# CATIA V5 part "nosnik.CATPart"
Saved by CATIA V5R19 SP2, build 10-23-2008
Part number: nosnik
Material "Steel": density 7860 kg/m3, Young's modulus 2e+11 Pa, Poisson ratio 0.266, thermal expansion 1.17e-05 1/K
Bounding box of the stored display mesh (mm): x -120 to 120, y -15 to 15, z -22.5 to 22.5
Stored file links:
  C:\Documents and Settings\JiriPesek\Dokumenty\catia\nosnik.CATPart
  D:\Program Files\Dassault Systemes\B19\intel_a\startup\materials\Catalog.CATMaterial
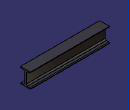
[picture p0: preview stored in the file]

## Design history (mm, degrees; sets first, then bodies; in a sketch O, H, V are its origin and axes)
AxisSystem1: origin (0, 0, 0), X (1, 0, 0), Y (0, 1, 0), Z (0, 0, 1)
Body1 (main body)
  Sketch1 on YZ plane of AxisSystem1, origin (0, 0, 0), H (0, 1, 0), V (0, 0, 1)
    line L1 (2.5, 14.7411) -> (2.5, -14.7411)
    construction line L2 (2.5, -18.4064) -> (-2.5, -18.4064)
    line L3 (-2.5, -14.7411) -> (-2.5, 14.7411)
    construction line L4 (-2.5, 18.4064) -> (2.5, 18.4064)
    point P1 (2.5, 18.4064)
    point P2 (2.5, -18.4064)
    point P3 (-2.5, -18.4064)
    point P4 (-2.5, 18.4064)
    point P5 (0, 20.3479)
    line L5 (15, 22.5) -> (15, 21.3327)
    line L6 (13.1743, 19.3403) -> (6.1514, 18.7258)
    line L7 (-15, 21.3327) -> (-15, 22.5)
    line L8 (-15, 22.5) -> (15, 22.5)
    point P8 (0, -20.3479)
    line L9 (15, -21.3327) -> (15, -22.5)
    line L10 (15, -22.5) -> (-15, -22.5)
    line L11 (-15, -22.5) -> (-15, -21.3327)
    line L12 (-13.1743, -19.3403) -> (-6.1514, -18.7258)
    point P9 (15, -19.5)
    point P11 (-15, -22.5)
    point P12 (-15, -19.5)
    line L13 (6.1514, -18.7258) -> (13.1743, -19.3403)
    line L14 (-6.1514, 18.7258) -> (-13.1743, 19.3403)
    arc A1 centre (6.5, -14.7411) radius 4 from (6.1514, -18.7258) to (2.5, -14.7411) cw
    arc A2 centre (-6.5, -14.7411) radius 4 from (-2.5, -14.7411) to (-6.1514, -18.7258) cw
    arc A3 centre (-6.5, 14.7411) radius 4 from (-2.5, 14.7411) to (-6.1514, 18.7258) ccw
    arc A4 centre (6.5, 14.7411) radius 4 from (6.1514, 18.7258) to (2.5, 14.7411) ccw
    arc A5 centre (13, -21.3327) radius 2 from (15, -21.3327) to (13.1743, -19.3403) ccw
    arc A6 centre (13, 21.3327) radius 2 from (15, 21.3327) to (13.1743, 19.3403) cw
    arc A7 centre (-13, 21.3327) radius 2 from (-15, 21.3327) to (-13.1743, 19.3403) ccw
    arc A8 centre (-13, -21.3327) radius 2 from (-15, -21.3327) to (-13.1743, -19.3403) cw
    distance L3 L1 = 5
    distance L7 L5 = 30
    distance L8 L10 = 45
    angle L12 L10 = 5
    radius A1 = 4
    radius A2 = 4 {= Sketch1.radius(A1)}
    radius A3 = 4 {= Sketch1.radius(A1)}
    radius A4 = 4 {= Sketch1.radius(A1)}
    radius A5 = 2
    radius A6 = 2 {= Sketch1.radius(A5)}
    radius A7 = 2 {= Sketch1.radius(A5)}
    distance P11 P12 = 3
    radius A8 = 2 {= Sketch1.radius(A5)}
    vertical: L1 V, L3 V, L5 V, L7 V, L9 V, L11 V
    horizontal: L2 H, L4 H, L8 H, L10 H
    equidistance: L1 L3 O, L2 L4 O, L5 L7 P5, L6 L8 P5, L9 L11 P8, L10 L12 P8
    coincidence: P5 V, P8 V, P9 L5, L13 P2, L1 P2, L3 P3, L12 P3, L3 P4, L14 P4, L6 P1, L1 P1, L9 P9, L13 P9, L11 P12, L12 P12
    symmetry: L8 L10 H, L14 L12 H, L13 L6 H, L6 L14 V
    tangency: A1 L13, A1 L1, A2 L3, A2 L12, A3 L3, A3 L14, A4 L6, A4 L1, A5 L9, A5 L13, A6 L5, A6 L6, A7 L7, A7 L14, A8 L11, A8 L12
  Pad1: profile Sketch1, direction (1, 0, 0), length 120, mirrored extent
